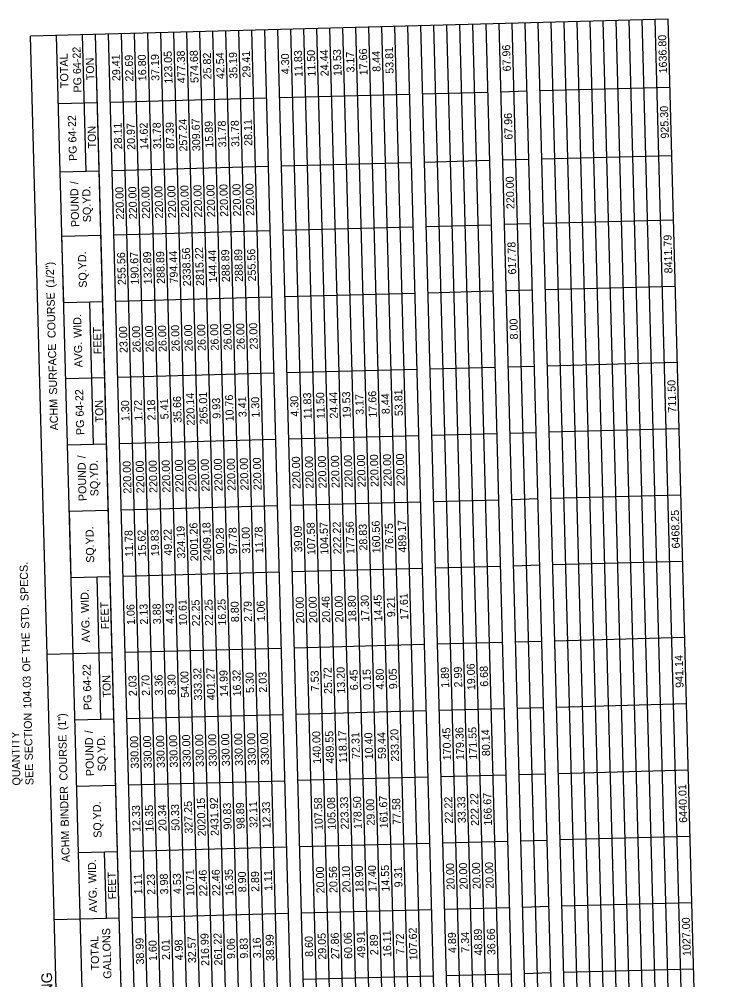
# Model space of a CAD drawing. Extents: x 1930091 to 1931962, y 596452 to 607874.
# Drawn here: x 1930662 to 1931189, y 602254 to 602974 of the extents above; entities that cross this region are included whole.
import ezdxf

# ---------------------------------------------------------------- set-up
doc = ezdxf.new("R2010")
doc.units = 0
doc.layers.add('Default', color=7, linetype='Continuous')

msp = doc.modelspace()

# ---------------------------------------------------------------- linework, layer by layer
at = {"layer": 'Default'}
for p, q in [((1931148.51, 602974.33), (1930670.93, 602961.51)), ((1931148.51, 602974.33), (1930670.93, 602961.51)), ((1930926.24, 601444.38), (1930885.35, 602967.27)), ((1930935.98, 601444.64), (1930895.1, 602967.53)), ((1930945.73, 601444.9), (1930904.85, 602967.79)), ((1930955.48, 601445.16), (1930914.59, 602968.05)), ((1930965.22, 601445.43), (1930924.34, 602968.32)), ((1930974.97, 601445.69), (1930934.09, 602968.58)), ((1930984.71, 601445.95), (1930943.83, 602968.84)), ((1930994.46, 601446.21), (1930953.58, 602969.1)), ((1930994.46, 601446.21), (1930953.58, 602969.1)), ((1931004.21, 601446.47), (1930963.33, 602969.36)), ((1931013.95, 601446.73), (1930973.07, 602969.62)), ((1931023.7, 601447), (1930982.82, 602969.89)), ((1931033.45, 601447.26), (1930992.57, 602970.15)), ((1931043.19, 601447.52), (1931002.31, 602970.41)), ((1931052.94, 601447.78), (1931012.06, 602970.67)), ((1931052.94, 601447.78), (1931012.06, 602970.67)), ((1931062.69, 601448.04), (1931021.81, 602970.93)), ((1931072.43, 601448.3), (1931031.55, 602971.19)), ((1931082.18, 601448.57), (1931041.3, 602971.46)), ((1931082.18, 601448.57), (1931041.3, 602971.46)), ((1931091.93, 601448.83), (1931051.05, 602971.72)), ((1931101.67, 601449.09), (1931060.79, 602971.98)), ((1931111.42, 601449.35), (1931070.54, 602972.24)), ((1931121.17, 601449.61), (1931080.28, 602972.5)), ((1931130.91, 601449.87), (1931090.03, 602972.76)), ((1931140.66, 601450.14), (1931099.78, 602973.02)), ((1931150.4, 601450.4), (1931109.52, 602973.29)), ((1931160.15, 601450.66), (1931119.27, 602973.55)), ((1931169.9, 601450.92), (1931129.02, 602973.81)), ((1931179.64, 601451.18), (1931138.76, 602974.07)), ((1931189.39, 601451.44), (1931148.51, 602974.33)), ((1930711.81, 601438.62), (1930670.93, 602961.51)), ((1930720.88, 601827.54), (1930690.43, 602962.04)), ((1930712.67, 602860.22), (1930709.92, 602962.56)), ((1930760.55, 601439.93), (1930719.66, 602962.82)), ((1930725.04, 602762.53), (1930719.66, 602962.82)), ((1930770.29, 601440.19), (1930729.41, 602963.08)), ((1930780.04, 601440.46), (1930739.16, 602963.34)), ((1930789.78, 601440.72), (1930748.9, 602963.61)), ((1930799.53, 601440.98), (1930758.65, 602963.87)), ((1930809.28, 601441.24), (1930768.4, 602964.13)), ((1930819.02, 601441.5), (1930778.14, 602964.39)), ((1930828.77, 601441.76), (1930787.89, 602964.65)), ((1930838.52, 601442.03), (1930797.64, 602964.91)), ((1930848.26, 601442.29), (1930807.38, 602965.18)), ((1930858.01, 601442.55), (1930817.13, 602965.44)), ((1930867.76, 601442.81), (1930826.88, 602965.7)), ((1930877.5, 601443.07), (1930836.62, 602965.96)), ((1930887.25, 601443.33), (1930846.37, 602966.22)), ((1930887.25, 601443.33), (1930846.37, 602966.22)), ((1930897, 601443.6), (1930856.12, 602966.48)), ((1930906.74, 601443.86), (1930865.86, 602966.75)), ((1930916.49, 601444.12), (1930875.61, 602967.01)), ((1930954.95, 602917.93), (1930857.49, 602915.32)), ((1930954.95, 602917.93), (1930857.49, 602915.32)), ((1931013.43, 602919.5), (1930964.7, 602918.19)), ((1931013.43, 602919.5), (1930964.7, 602918.19)), ((1931042.67, 602920.29), (1931023.18, 602919.76)), ((1931042.67, 602920.29), (1931023.18, 602919.76)), ((1931149.88, 602923.16), (1931052.42, 602920.55)), ((1931149.88, 602923.16), (1931052.42, 602920.55)), ((1930721.04, 602911.65), (1930691.8, 602910.87)), ((1930847.74, 602915.05), (1930730.78, 602911.91)), ((1930847.74, 602915.05), (1930730.78, 602911.91)), ((1930956.33, 602866.76), (1930858.86, 602864.15)), ((1930956.33, 602866.76), (1930858.86, 602864.15)), ((1931014.81, 602868.33), (1930966.07, 602867.02)), ((1931014.81, 602868.33), (1930966.07, 602867.02)), ((1931044.05, 602869.12), (1931024.55, 602868.59)), ((1931044.05, 602869.12), (1931024.55, 602868.59)), ((1931151.26, 602872), (1931053.79, 602869.38)), ((1931151.26, 602872), (1931053.79, 602869.38)), ((1930722.41, 602860.48), (1930693.17, 602859.7)), ((1930849.12, 602863.88), (1930732.16, 602860.74)), ((1930849.12, 602863.88), (1930732.16, 602860.74)), ((1931152.55, 602823.75), (1931055.09, 602821.13)), ((1931152.55, 602823.75), (1931055.09, 602821.13)), ((1930957.62, 602818.52), (1930860.16, 602815.9)), ((1930957.62, 602818.52), (1930860.16, 602815.9)), ((1931016.1, 602820.09), (1930967.37, 602818.78)), ((1931016.1, 602820.09), (1930967.37, 602818.78)), ((1931045.34, 602820.87), (1931025.85, 602820.35)), ((1931045.34, 602820.87), (1931025.85, 602820.35)), ((1930723.71, 602812.24), (1930694.47, 602811.45)), ((1930695.8, 602761.75), (1930694.47, 602811.45)), ((1930850.41, 602815.64), (1930733.45, 602812.5)), ((1930850.41, 602815.64), (1930733.45, 602812.5)), ((1931153.89, 602774.04), (1931056.42, 602771.43)), ((1931153.89, 602774.04), (1931056.42, 602771.43)), ((1930851.75, 602765.93), (1930734.79, 602762.79)), ((1930851.75, 602765.93), (1930734.79, 602762.79)), ((1930958.96, 602768.81), (1930861.49, 602766.19)), ((1930958.96, 602768.81), (1930861.49, 602766.19)), ((1931017.44, 602770.38), (1930968.7, 602769.07)), ((1931017.44, 602770.38), (1930968.7, 602769.07)), ((1931046.68, 602771.16), (1931027.18, 602770.64)), ((1931046.68, 602771.16), (1931027.18, 602770.64)), ((1930725.04, 602762.53), (1930695.8, 602761.75)), ((1930725.04, 602762.53), (1930715.29, 602762.27)), ((1930718.16, 602655.55), (1930715.29, 602762.27)), ((1930730.57, 602556.39), (1930725.04, 602762.53)), ((1931155.42, 602717.03), (1931057.95, 602714.41)), ((1931155.42, 602717.03), (1931057.95, 602714.41)), ((1930853.28, 602708.92), (1930736.32, 602705.78)), ((1930853.28, 602708.92), (1930736.32, 602705.78)), ((1930960.49, 602711.79), (1930863.02, 602709.18)), ((1930960.49, 602711.79), (1930863.02, 602709.18)), ((1931018.97, 602713.36), (1930970.23, 602712.05)), ((1931018.97, 602713.36), (1930970.23, 602712.05)), ((1931048.21, 602714.15), (1931028.71, 602713.62)), ((1931048.21, 602714.15), (1931028.71, 602713.62)), ((1930726.57, 602705.51), (1930697.33, 602704.73)), ((1930726.57, 602705.51), (1930716.83, 602705.25)), ((1931156.75, 602667.32), (1931059.29, 602664.7)), ((1931156.75, 602667.32), (1931059.29, 602664.7)), ((1930854.61, 602659.21), (1930737.65, 602656.07)), ((1930854.61, 602659.21), (1930737.65, 602656.07)), ((1930961.82, 602662.09), (1930864.36, 602659.47)), ((1930961.82, 602662.09), (1930864.36, 602659.47)), ((1931020.3, 602663.66), (1930971.57, 602662.35)), ((1931020.3, 602663.66), (1930971.57, 602662.35)), ((1931049.54, 602664.44), (1931030.05, 602663.92)), ((1931049.54, 602664.44), (1931030.05, 602663.92)), ((1930727.91, 602655.81), (1930698.67, 602655.02)), ((1931050.87, 602614.73), (1931031.38, 602614.21)), ((1931050.87, 602614.73), (1931031.38, 602614.21)), ((1931158.09, 602617.61), (1931060.62, 602615)), ((1931158.09, 602617.61), (1931060.62, 602615)), ((1930855.94, 602609.5), (1930738.99, 602606.36)), ((1930855.94, 602609.5), (1930738.99, 602606.36)), ((1930963.16, 602612.38), (1930865.69, 602609.76)), ((1930963.16, 602612.38), (1930865.69, 602609.76)), ((1931021.64, 602613.95), (1930972.9, 602612.64)), ((1931021.64, 602613.95), (1930972.9, 602612.64)), ((1930729.24, 602606.1), (1930700, 602605.31)), ((1930701.34, 602555.61), (1930700, 602605.31)), ((1931022.97, 602564.24), (1930974.24, 602562.93)), ((1931022.97, 602564.24), (1930974.24, 602562.93)), ((1931052.21, 602565.03), (1931032.72, 602564.5)), ((1931052.21, 602565.03), (1931032.72, 602564.5)), ((1931159.42, 602567.9), (1931061.96, 602565.29)), ((1931159.42, 602567.9), (1931061.96, 602565.29)), ((1930857.28, 602559.79), (1930740.32, 602556.65)), ((1930857.28, 602559.79), (1930740.32, 602556.65)), ((1930964.49, 602562.67), (1930867.03, 602560.06)), ((1930964.49, 602562.67), (1930867.03, 602560.06)), ((1930730.57, 602556.39), (1930701.34, 602555.61)), ((1930730.57, 602556.39), (1930720.83, 602556.13)), ((1930723.69, 602449.41), (1930720.83, 602556.13)), ((1930736.11, 602350.25), (1930730.57, 602556.39)), ((1931024.5, 602507.22), (1930975.77, 602505.92)), ((1931024.5, 602507.22), (1930975.77, 602505.92)), ((1931053.74, 602508.01), (1931034.25, 602507.49)), ((1931053.74, 602508.01), (1931034.25, 602507.49)), ((1931160.95, 602510.89), (1931063.49, 602508.27)), ((1931160.95, 602510.89), (1931063.49, 602508.27)), ((1930732.11, 602499.38), (1930683.37, 602498.07)), ((1930732.11, 602499.38), (1930722.36, 602499.11)), ((1930858.81, 602502.78), (1930741.85, 602499.64)), ((1930858.81, 602502.78), (1930741.85, 602499.64)), ((1930966.02, 602505.65), (1930868.56, 602503.04)), ((1930966.02, 602505.65), (1930868.56, 602503.04)), ((1930702.87, 602498.59), (1930683.37, 602498.07)), ((1931025.83, 602457.52), (1930977.1, 602456.21)), ((1931025.83, 602457.52), (1930977.1, 602456.21)), ((1931055.07, 602458.3), (1931035.58, 602457.78)), ((1931055.07, 602458.3), (1931035.58, 602457.78)), ((1931162.29, 602461.18), (1931064.82, 602458.56)), ((1931162.29, 602461.18), (1931064.82, 602458.56)), ((1930733.44, 602449.67), (1930704.2, 602448.88)), ((1930860.14, 602453.07), (1930743.19, 602449.93)), ((1930860.14, 602453.07), (1930743.19, 602449.93)), ((1930967.36, 602455.95), (1930869.89, 602453.33)), ((1930967.36, 602455.95), (1930869.89, 602453.33)), ((1930968.69, 602406.24), (1930871.22, 602403.62)), ((1930968.69, 602406.24), (1930871.22, 602403.62)), ((1931027.17, 602407.81), (1930978.44, 602406.5)), ((1931027.17, 602407.81), (1930978.44, 602406.5)), ((1931056.41, 602408.6), (1931036.92, 602408.07)), ((1931056.41, 602408.6), (1931036.92, 602408.07)), ((1931163.62, 602411.47), (1931066.15, 602408.86)), ((1931163.62, 602411.47), (1931066.15, 602408.86)), ((1930734.77, 602399.96), (1930705.53, 602399.18)), ((1930861.48, 602403.36), (1930744.52, 602400.22)), ((1930861.48, 602403.36), (1930744.52, 602400.22)), ((1930970.02, 602356.53), (1930872.56, 602353.92)), ((1930970.02, 602356.53), (1930872.56, 602353.92)), ((1931028.5, 602358.1), (1930979.77, 602356.8)), ((1931028.5, 602358.1), (1930979.77, 602356.8)), ((1931057.74, 602358.89), (1931038.25, 602358.37)), ((1931057.74, 602358.89), (1931038.25, 602358.37)), ((1931164.95, 602361.77), (1931067.49, 602359.15)), ((1931164.95, 602361.77), (1931067.49, 602359.15)), ((1930736.11, 602350.25), (1930706.87, 602349.47)), ((1930736.11, 602350.25), (1930726.36, 602349.99)), ((1930727.7, 602300.29), (1930726.36, 602349.99)), ((1930740.11, 602201.13), (1930736.11, 602350.25)), ((1930862.81, 602353.66), (1930745.85, 602350.52)), ((1930862.81, 602353.66), (1930745.85, 602350.52)), ((1930971.36, 602306.83), (1930873.89, 602304.21)), ((1930971.36, 602306.83), (1930873.89, 602304.21)), ((1931029.84, 602308.4), (1930981.11, 602307.09)), ((1931029.84, 602308.4), (1930981.11, 602307.09)), ((1931059.08, 602309.18), (1931039.58, 602308.66)), ((1931059.08, 602309.18), (1931039.58, 602308.66)), ((1931166.29, 602312.06), (1931068.82, 602309.44)), ((1931166.29, 602312.06), (1931068.82, 602309.44)), ((1930737.44, 602300.55), (1930688.71, 602299.24)), ((1930864.15, 602303.95), (1930747.19, 602300.81)), ((1930864.15, 602303.95), (1930747.19, 602300.81)), ((1931167.62, 602262.35), (1931070.16, 602259.74)), ((1931157.88, 602262.09), (1931070.16, 602259.74)), ((1930972.69, 602257.12), (1930875.23, 602254.5)), ((1930972.69, 602257.12), (1930875.23, 602254.5)), ((1931031.17, 602258.69), (1930982.44, 602257.38)), ((1931031.17, 602258.69), (1930982.44, 602257.38)), ((1931060.41, 602259.47), (1931040.92, 602258.95)), ((1931060.41, 602259.47), (1931040.92, 602258.95))]:
    msp.add_line(p, q, dxfattribs=at)

# ---------------------------------------------------------------- texts
for s, height, p in [('1636.80', 6, (1931147.72, 602933.77)), (' 64-22', 6, (1930708.89, 602931.06)), ('53.81', 6, (1930942.91, 602933.49)), ('67.96', 6, (1931030.64, 602935.27)), ('TOTAL', 6, (1930699.36, 602922.82)), ('29.41', 6, (1930738.23, 602928)), ('22.69', 6, (1930747.99, 602927.68)), ('16.80', 6, (1930757.74, 602927.95)), ('37.19', 6, (1930767.49, 602928.2)), ('123.05', 6, (1930777.3, 602926.11)), ('477.38', 6, (1930787.04, 602926.39)), ('574.68', 6, (1930796.79, 602926.66)), ('25.82', 6, (1930806.47, 602929.28)), ('42.54', 6, (1930816.22, 602929.53)), ('35.19', 6, (1930825.96, 602929.77)), ('29.41', 6, (1930835.7, 602930.62)), ('4.30', 6, (1930864.89, 602933.16)), ('11.83', 6, (1930874.7, 602931.08)), ('11.50', 6, (1930884.44, 602931.36)), ('24.44', 6, (1930894.19, 602931.62)), ('19.53', 6, (1930903.94, 602931.87)), ('3.17', 6, (1930913.62, 602934.46)), ('17.66', 6, (1930923.43, 602932.39)), ('8.44', 6, (1930933.11, 602934.99)), ('TON', 6, (1930718.71, 602928.68)), ('PG', 6, (1930709.2, 602919.46)), ('67.96', 6, (1931032.01, 602884.1)), ('925.30', 6, (1931149.03, 602884.93)), (' 64-22', 6, (1930705.39, 602879.76)), ('28.11', 6, (1930739.6, 602876.83)), ('20.97', 6, (1930749.37, 602876.51)), ('14.62', 6, (1930759.11, 602876.81)), ('31.78', 6, (1930768.86, 602877.03)), ('87.39', 6, (1930778.61, 602877.29)), ('257.24', 6, (1930788.41, 602875.24)), ('309.67', 6, (1930798.16, 602875.49)), ('15.89', 6, (1930807.85, 602878.08)), ('31.78', 6, (1930817.59, 602878.34)), ('31.78', 6, (1930827.34, 602878.6)), ('28.11', 6, (1930837.07, 602879.45)), ('TON', 6, (1930720.08, 602877.51)), ('PG', 6, (1930705.7, 602868.16)), (' /', 6, (1930706.6, 602848.52)), ('220.00', 6, (1931033.41, 602832.07)), ('POUND', 6, (1930707.4, 602818.67)), ('SQ.YD.', 6, (1930716.31, 602822.25)), ('220.00', 6, (1930741.02, 602824.23)), ('220.00', 6, (1930750.76, 602824.49)), ('220.00', 6, (1930760.51, 602824.75)), ('220.00', 6, (1930770.26, 602825.01)), ('220.00', 6, (1930780, 602825.27)), ('220.00', 6, (1930789.75, 602825.53)), ('220.00', 6, (1930799.5, 602825.79)), ('220.00', 6, (1930809.24, 602826.06)), ('220.00', 6, (1930818.99, 602826.32)), ('220.00', 6, (1930828.73, 602826.58)), ('220.00', 6, (1930838.48, 602826.84)), ('8411.79', 6, (1931151.75, 602783.9)), ('2338.56', 6, (1930791.13, 602774.22)), ('2815.22', 6, (1930800.87, 602774.51)), ('288.89', 6, (1930830.05, 602777.59)), ('255.56', 6, (1930839.8, 602777.85)), ('617.78', 6, (1931034.73, 602783.08)), ('SQ.YD.', 6, (1930713.13, 602773.16)), ('255.56', 6, (1930742.33, 602775.24)), ('190.67', 6, (1930752.08, 602775.5)), ('132.89', 6, (1930761.82, 602775.76)), ('288.89', 6, (1930771.57, 602776.02)), ('794.44', 6, (1930781.32, 602776.3)), ('144.44', 6, (1930810.56, 602777.08)), ('288.89', 6, (1930820.3, 602777.33)), (' (1/2")', 6, (1930688.8, 602770.96)), (' COURSE', 6, (1930689.82, 602733.19)), (' WID.', 6, (1930709.32, 602733.35)), ('26.00', 6, (1930753.45, 602724.48)), ('26.00', 6, (1930763.19, 602724.74)), ('26.00', 6, (1930772.94, 602725)), ('26.00', 6, (1930782.69, 602725.26)), ('26.00', 6, (1930792.43, 602725.52)), ('26.00', 6, (1930802.18, 602725.79)), ('26.00', 6, (1930811.93, 602726.05)), ('26.00', 6, (1930821.67, 602726.31)), ('26.00', 6, (1930831.42, 602726.57)), ('23.00', 6, (1930841.17, 602726.83)), ('8.00', 6, (1931036.03, 602734.39)), ('FEET', 6, (1930724.22, 602723.35)), ('23.00', 6, (1930743.7, 602724.22)), (' SURFACE', 6, (1930690.95, 602690.76)), ('AVG.', 6, (1930709.85, 602713.44)), ('711.50', 6, (1931154.55, 602679.52)), (' 64-22', 6, (1930710.9, 602674.35)), ('220.14', 6, (1930793.93, 602669.84)), ('265.01', 6, (1930803.66, 602670.66)), ('11.83', 6, (1930881.58, 602674.51)), ('11.50', 6, (1930891.33, 602674.78)), ('24.44', 6, (1930901.08, 602675.04)), ('19.53', 6, (1930910.82, 602675.29)), ('17.66', 6, (1930930.32, 602675.81)), ('8.44', 6, (1930940, 602678.42)), ('53.81', 6, (1930949.79, 602676.92)), ('ACHM', 6, (1930691.61, 602666.22)), ('TON', 6, (1930725.59, 602672.1)), ('1.30', 6, (1930745.07, 602673.18)), ('1.72', 6, (1930754.82, 602673.47)), ('2.18', 6, (1930764.56, 602673.69)), ('5.41', 6, (1930774.3, 602674.54)), ('35.66', 6, (1930784.12, 602671.89)), ('9.93', 6, (1930813.3, 602675)), ('10.76', 6, (1930823.11, 602672.94)), ('3.41', 6, (1930832.77, 602676.11)), ('1.30', 6, (1930842.54, 602675.8)), ('4.30', 6, (1930871.78, 602676.58)), ('3.17', 6, (1930920.51, 602677.88)), ('PG', 6, (1930711.21, 602662.75)), (' /', 6, (1930712.12, 602643.12)), ('SQ.YD.', 6, (1930721.82, 602616.85)), ('220.00', 6, (1930766.02, 602619.34)), ('220.00', 6, (1930775.77, 602619.6)), ('220.00', 6, (1930785.52, 602619.86)), ('220.00', 6, (1930795.26, 602620.13)), ('220.00', 6, (1930805.01, 602620.39)), ('220.00', 6, (1930814.76, 602620.65)), ('220.00', 6, (1930824.5, 602620.91)), ('220.00', 6, (1930834.25, 602621.17)), ('220.00', 6, (1930844, 602621.43)), ('220.00', 6, (1930873.23, 602622.22)), ('220.00', 6, (1930882.98, 602622.48)), ('220.00', 6, (1930892.73, 602622.74)), ('220.00', 6, (1930902.47, 602623)), ('220.00', 6, (1930912.22, 602623.27)), ('220.00', 6, (1930921.97, 602623.53)), ('220.00', 6, (1930931.71, 602623.79)), ('220.00', 6, (1930941.46, 602624.05)), ('220.00', 6, (1930951.21, 602624.31)), ('POUND', 6, (1930712.92, 602613.26)), ('220.00', 6, (1930746.53, 602618.82)), ('220.00', 6, (1930756.28, 602619.08)), ('6468.25', 6, (1931157.28, 602577.69)), ('SQ.YD.', 6, (1930718.66, 602567.02)), ('324.19', 6, (1930786.85, 602570.14)), ('2001.26', 6, (1930796.66, 602568.08)), ('2409.18', 6, (1930806.41, 602568.34)), ('90.28', 6, (1930816.03, 602573.26)), ('97.78', 6, (1930825.77, 602573.52)), ('31.00', 6, (1930835.52, 602573.79)), ('11.78', 6, (1930845.27, 602574.04)), ('39.09', 6, (1930874.51, 602574.83)), ('107.58', 6, (1930884.32, 602572.76)), ('104.57', 6, (1930894.06, 602573.02)), ('222.22', 6, (1930903.81, 602573.32)), ('177.56', 6, (1930913.56, 602573.55)), ('28.83', 6, (1930923.24, 602576.14)), ('160.56', 6, (1930933.05, 602574.07)), ('76.75', 6, (1930942.73, 602576.64)), ('489.17', 6, (1930952.54, 602574.59)), ('11.78', 6, (1930747.8, 602571.42)), ('15.62', 6, (1930757.55, 602571.72)), ('19.83', 6, (1930767.3, 602571.95)), ('49.22', 6, (1930777.04, 602572.25)), (' SPECS.', 6, (1930669.52, 602536.03)), (' WID.', 6, (1930714.85, 602527.22)), ('17.30', 6, (1930924.67, 602522.79)), ('14.45', 6, (1930934.42, 602523.01)), ('17.61', 6, (1930953.9, 602524.14)), ('FEET', 6, (1930729.75, 602517.21)), ('1.06', 6, (1930749.17, 602520.4)), ('2.13', 6, (1930758.92, 602520.66)), ('3.88', 6, (1930768.67, 602520.91)), ('4.43', 6, (1930778.41, 602521.18)), ('10.61', 6, (1930788.21, 602519.69)), ('22.25', 6, (1930797.97, 602519.35)), ('22.25', 6, (1930807.71, 602519.61)), ('16.25', 6, (1930817.46, 602519.88)), ('8.80', 6, (1930827.14, 602522.5)), ('2.79', 6, (1930836.89, 602522.75)), ('1.06', 6, (1930846.64, 602523.01)), ('20.00', 6, (1930875.94, 602521.48)), ('20.00', 6, (1930885.69, 602521.74)), ('20.46', 6, (1930895.43, 602521.99)), ('20.00', 6, (1930905.18, 602522.26)), ('18.80', 6, (1930914.93, 602522.53)), ('9.21', 6, (1930944.09, 602526.21)), (' STD.', 6, (1930670.07, 602515.34)), ('AVG.', 6, (1930715.39, 602507.3)), (' THE', 6, (1930670.57, 602496.7)), (' OF', 6, (1930670.94, 602483.11)), ('941.14', 6, (1931160.09, 602473.27)), (' 64-22', 6, (1930716.44, 602468.22)), ('54.00', 6, (1930789.65, 602465.76)), ('333.32', 6, (1930799.46, 602463.72)), ('401.27', 6, (1930809.21, 602463.95)), ('14.99', 6, (1930818.89, 602466.53)), ('16.32', 6, (1930828.64, 602466.83)), ('7.53', 6, (1930887.06, 602470.7)), ('25.72', 6, (1930896.86, 602468.66)), ('13.20', 6, (1930906.61, 602468.9)), ('6.45', 6, (1930916.3, 602471.46)), ('0.15', 6, (1930926.04, 602471.72)), ('4.80', 6, (1930935.79, 602472.02)), ('9.05', 6, (1930945.54, 602472.24)), ('1.89', 6, (1930984.52, 602473.31)), ('2.99', 6, (1930994.27, 602473.57)), ('19.06', 6, (1931004.08, 602471.51)), ('6.68', 6, (1931013.76, 602474.09)), (' 104.03', 6, (1930671.68, 602455.55)), ('TON', 6, (1930731.13, 602465.96)), ('2.03', 6, (1930750.6, 602467.03)), ('2.70', 6, (1930760.35, 602467.31)), ('3.36', 6, (1930770.1, 602467.56)), ('8.30', 6, (1930779.84, 602467.83)), ('5.30', 6, (1930838.32, 602469.4)), ('2.03', 6, (1930848.07, 602469.65)), ('PG', 6, (1930716.75, 602456.61)), (' SECTION', 6, (1930672.72, 602416.65)), (' (1")', 6, (1930697.7, 602439.31)), ('233.20', 6, (1930946.99, 602417.91)), ('170.45', 6, (1930985.98, 602418.92)), ('179.36', 6, (1930995.73, 602419.21)), ('171.55', 6, (1931005.47, 602419.45)), ('80.14', 6, (1931015.16, 602422.08)), ('QUANTITY', 6, (1930663.41, 602400.07)), (' COURSE', 6, (1930698.72, 602401.54)), (' /', 6, (1930717.65, 602436.98)), ('POUND', 6, (1930718.45, 602407.12)), ('SQ.YD.', 6, (1930727.36, 602410.71)), ('330.00', 6, (1930752.06, 602412.68)), ('330.00', 6, (1930761.81, 602412.94)), ('330.00', 6, (1930771.56, 602413.2)), ('330.00', 6, (1930781.3, 602413.46)), ('330.00', 6, (1930791.05, 602413.73)), ('330.00', 6, (1930800.8, 602413.99)), ('330.00', 6, (1930810.54, 602414.25)), ('330.00', 6, (1930820.29, 602414.51)), ('330.00', 6, (1930830.04, 602414.77)), ('330.00', 6, (1930839.78, 602415.03)), ('330.00', 6, (1930849.53, 602415.3)), ('140.00', 6, (1930888.51, 602416.34)), ('489.55', 6, (1930898.26, 602416.57)), ('118.17', 6, (1930908.01, 602416.85)), ('72.31', 6, (1930917.68, 602420.03)), ('10.40', 6, (1930927.44, 602419.72)), ('59.44', 6, (1930937.18, 602419.98)), ('SEE', 6, (1930673.16, 602400.33)), (' BINDER', 6, (1930699.64, 602367.12)), ('6440.01', 6, (1931162.8, 602372.11)), ('223.33', 6, (1930909.34, 602367.15)), ('178.50', 6, (1930919.09, 602367.42)), ('161.67', 6, (1930938.58, 602367.93)), ('33.33', 6, (1930997, 602371.83)), ('222.22', 6, (1931006.81, 602369.8)), ('166.67', 6, (1931016.55, 602370.03)), ('SQ.YD.', 6, (1930724.19, 602360.88)), ('12.33', 6, (1930753.34, 602365.29)), ('16.35', 6, (1930763.08, 602365.53)), ('20.34', 6, (1930772.83, 602365.83)), ('50.33', 6, (1930782.58, 602366.08)), ('327.25', 6, (1930792.39, 602363.98)), ('2020.15', 6, (1930802.19, 602361.92)), ('2431.92', 6, (1930811.94, 602362.23)), ('90.83', 6, (1930821.56, 602367.12)), ('98.89', 6, (1930831.31, 602367.38)), ('32.11', 6, (1930841.04, 602368.23)), ('12.33', 6, (1930850.8, 602367.91)), ('107.58', 6, (1930889.85, 602366.62)), ('105.08', 6, (1930899.6, 602366.88)), ('29.00', 6, (1930928.77, 602370.01)), ('77.58', 6, (1930948.27, 602370.52)), ('22.22', 6, (1930987.25, 602371.6)), ('ACHM', 6, (1930700.3, 602342.58)), (' WID.', 6, (1930720.29, 602324.73)), ('20.00', 6, (1930988.59, 602321.87)), ('20.00', 6, (1930998.33, 602322.14)), ('20.00', 6, (1931008.08, 602322.4)), ('20.00', 6, (1931017.83, 602322.66)), ('FEET', 6, (1930735.19, 602314.73)), ('1.11', 6, (1930754.59, 602318.49)), ('4.53', 6, (1930783.85, 602318.7)), ('10.71', 6, (1930793.64, 602317.21)), ('22.46', 6, (1930803.4, 602316.89)), ('22.46', 6, (1930813.15, 602317.15)), ('16.35', 6, (1930822.9, 602317.39)), ('8.90', 6, (1930832.58, 602320.02)), ('2.89', 6, (1930842.33, 602320.26)), ('1.11', 6, (1930852.06, 602321.11)), ('20.00', 6, (1930891.12, 602319.26)), ('20.56', 6, (1930900.87, 602319.51)), ('20.10', 6, (1930910.61, 602319.78)), ('18.90', 6, (1930920.36, 602320.04)), ('17.40', 6, (1930930.11, 602320.3)), ('14.55', 6, (1930939.85, 602320.53)), ('9.31', 6, (1930949.52, 602323.73)), ('2.23', 6, (1930764.35, 602318.17)), ('3.98', 6, (1930774.1, 602318.43)), ('AVG.', 6, (1930720.82, 602304.82)), ('1027.00', 6, (1931165.48, 602272.22)), ('GALLONS', 6, (1930731.53, 602255.22)), ('49.91', 6, (1930921.68, 602270.9)), ('16.11', 6, (1930941.17, 602271.43)), ('107.62', 6, (1930960.74, 602269.07)), ('48.89', 6, (1931009.41, 602272.67)), ('36.66', 6, (1931019.16, 602272.94)), ('TOTAL', 6, (1930722.36, 602261.42)), ('38.99', 6, (1930756, 602265.87)), ('1.60', 6, (1930765.69, 602268.48)), ('2.01', 6, (1930775.42, 602269.31)), ('4.98', 6, (1930785.18, 602268.99)), ('32.57', 6, (1930794.99, 602266.92)), ('216.99', 6, (1930804.8, 602264.85)), ('261.22', 6, (1930814.55, 602265.15)), ('9.06', 6, (1930824.17, 602270.04)), ('9.83', 6, (1930833.91, 602270.3)), ('3.16', 6, (1930843.66, 602270.56)), ('38.99', 6, (1930853.47, 602268.49)), ('8.60', 6, (1930882.65, 602271.62)), ('29.05', 6, (1930892.46, 602269.52)), ('27.86', 6, (1930902.2, 602269.8)), ('60.06', 6, (1930911.95, 602270.06)), ('2.89', 6, (1930931.38, 602272.91)), ('7.72', 6, (1930950.87, 602273.47)), ('4.89', 6, (1930989.86, 602274.48)), ('7.34', 6, (1930999.6, 602274.76)), (' SURFACING', 8, (1930688.7, 602194.19))]:
    msp.add_text(s, height=height, rotation=91.53769, dxfattribs=at).set_placement(p)

doc.saveas('drawing.dxf')
